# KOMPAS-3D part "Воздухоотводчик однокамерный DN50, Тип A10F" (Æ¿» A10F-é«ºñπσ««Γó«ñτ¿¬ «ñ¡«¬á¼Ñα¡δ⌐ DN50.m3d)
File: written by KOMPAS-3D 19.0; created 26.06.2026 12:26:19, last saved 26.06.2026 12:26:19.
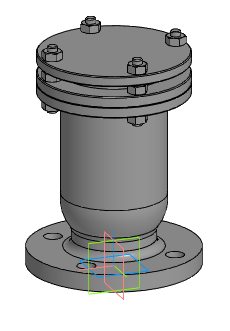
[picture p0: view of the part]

Document properties: Автор: Энергия; Полное имя файла: Z:\3.Личные\kachalov\001_3d для проектировщиков\х.х Тип A10F Воздухоотводчик однокамерный фланцевый\_step\Тип A10F-Воздухоотводчик однокамерный DN50.m3d

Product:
- Part/product: Воздухоотводчик однокамерный DN50  | designation Тип A10F

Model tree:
1. Операция без истории:1  (labels: Тип A10F; Воздухоотводчик однокамерный DN50)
